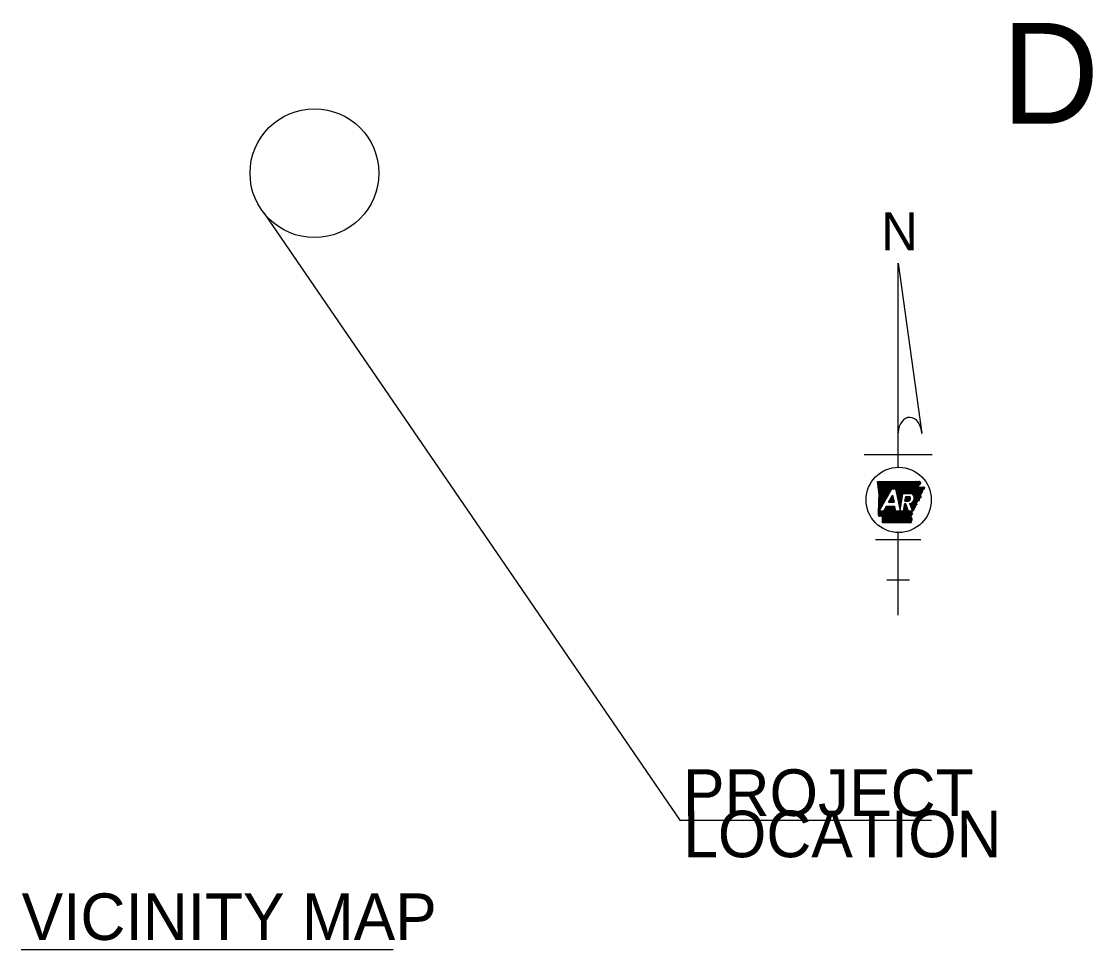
# Model space of a CAD drawing. Extents: x 171 to 3403, y 68 to 2102.
# Drawn here: x 430 to 1255, y 1234 to 1952 of the extents above; entities that cross this region are included whole.
import ezdxf

# ---------------------------------------------------------------- set-up
doc = ezdxf.new("R2010")
doc.units = 0
for name, color, linetype in [('1', 7, 'Continuous'), ('2', 7, 'Continuous'), ('R_Draft', 7, 'Continuous')]:
    doc.layers.add(name, color=color, linetype=linetype)

msp = doc.modelspace()

# ---------------------------------------------------------------- linework, layer by layer
at = {"layer": '1'}
for p, q in [((617.82, 1803.59), (939.58, 1334.32)), ((939.58, 1334.32), (1134.19, 1334.32)), ((430.38, 1234.3), (717.82, 1234.3))]:
    msp.add_line(p, q, dxfattribs=at)
msp.add_circle((656.98, 1834.34), 49.79, dxfattribs=at)
at = {"layer": 'R_Draft'}
for p, q in [((1108.29, 1764.75), (1126.48, 1633.28)), ((1108.29, 1607.09), (1108.29, 1764.75)), ((1081.96, 1616.84), (1134.61, 1616.84)), ((1092.32, 1595.8), (1092.53, 1596.02)), ((1092.39, 1595.18), (1093.23, 1596.02)), ((1092.47, 1594.56), (1093.93, 1596.02)), ((1092.55, 1593.94), (1094.62, 1596.02)), ((1092.63, 1593.32), (1095.32, 1596.01)), ((1092.7, 1592.7), (1096.02, 1596.01)), ((1092.78, 1592.08), (1096.71, 1596.01)), ((1092.86, 1591.46), (1097.41, 1596.01)), ((1092.93, 1590.84), (1098.11, 1596.01)), ((1093.01, 1590.22), (1098.8, 1596.01)), ((1093.09, 1589.6), (1099.5, 1596.01)), ((1093.17, 1588.98), (1100.2, 1596.01)), ((1093.24, 1588.36), (1100.89, 1596.01)), ((1093.32, 1587.74), (1101.59, 1596.01)), ((1093.34, 1580.8), (1108.57, 1596.02)), ((1093.37, 1581.52), (1107.87, 1596.02)), ((1093.39, 1582.24), (1107.17, 1596.02)), ((1093.4, 1587.12), (1102.29, 1596.01)), ((1093.42, 1582.96), (1106.48, 1596.02)), ((1093.44, 1583.68), (1105.78, 1596.02)), ((1093.46, 1584.4), (1105.08, 1596.02)), ((1093.47, 1586.5), (1102.98, 1596.01)), ((1093.49, 1585.12), (1104.38, 1596.02)), ((1093.51, 1585.84), (1103.68, 1596.01)), ((1103.69, 1590.45), (1109.27, 1596.03)), ((1104.39, 1590.45), (1109.97, 1596.03)), ((1105.09, 1590.45), (1110.67, 1596.03)), ((1105.78, 1590.45), (1111.38, 1596.04)), ((1106.22, 1590.19), (1112.09, 1596.06)), ((1106.34, 1589.61), (1112.79, 1596.07)), ((1106.46, 1589.04), (1113.5, 1596.08)), ((1106.59, 1588.46), (1114.21, 1596.09)), ((1106.71, 1587.89), (1114.92, 1596.1)), ((1106.83, 1587.32), (1115.63, 1596.11)), ((1106.95, 1586.74), (1116.33, 1596.12)), ((1107.08, 1586.17), (1117.04, 1596.13)), ((1107.2, 1585.59), (1117.75, 1596.14)), ((1107.32, 1585.02), (1118.46, 1596.15)), ((1107.45, 1584.45), (1119.16, 1596.17)), ((1107.57, 1583.87), (1119.87, 1596.18)), ((1107.69, 1583.3), (1120.58, 1596.19)), ((1107.81, 1582.72), (1121.3, 1596.21)), ((1112.66, 1586.87), (1122.01, 1596.22)), ((1113.35, 1586.87), (1122.72, 1596.24)), ((1114.05, 1586.87), (1123.44, 1596.26)), ((1114.75, 1586.87), (1124.15, 1596.27)), ((1115.44, 1586.87), (1124.86, 1596.29)), ((1116.14, 1586.87), (1125.02, 1595.75)), ((1116.84, 1586.87), (1125.36, 1595.39)), ((1117.53, 1586.87), (1125.45, 1594.78)), ((1118.23, 1586.87), (1123.85, 1592.49)), ((1118.86, 1586.8), (1123.72, 1591.66)), ((1119.24, 1586.49), (1124.45, 1591.7)), ((1119.58, 1586.13), (1125.19, 1591.73)), ((1119.88, 1585.74), (1125.92, 1591.77)), ((1120.14, 1585.3), (1126.66, 1591.81)), ((1120.36, 1584.81), (1127.39, 1591.85)), ((1120.52, 1584.28), (1128.05, 1591.81)), ((1120.61, 1583.67), (1128.38, 1591.44)), ((1093.22, 1577.19), (1099.08, 1583.05)), ((1093.25, 1577.91), (1099.99, 1584.66)), ((1093.27, 1578.64), (1100.9, 1586.27)), ((1093.3, 1579.36), (1101.81, 1587.87)), ((1093.32, 1580.08), (1102.72, 1589.48)), ((1093.55, 1573.28), (1103.27, 1590.45)), ((1100.7, 1580.02), (1103.88, 1585.64)), ((1100.74, 1580.02), (1104.32, 1583.6)), ((1101.43, 1580.02), (1104.44, 1583.03)), ((1101.57, 1581.55), (1104.19, 1584.18)), ((1102.48, 1583.16), (1104.07, 1584.75)), ((1103.27, 1590.45), (1106.16, 1590.45)), ((1103.39, 1584.76), (1103.95, 1585.32)), ((1107.94, 1582.15), (1111.89, 1586.1)), ((1108.06, 1581.58), (1111.74, 1585.26)), ((1108.18, 1581), (1111.6, 1584.42)), ((1108.31, 1580.43), (1111.45, 1583.57)), ((1112.02, 1586.87), (1118.78, 1586.87)), ((1113.49, 1580.78), (1117.16, 1584.45)), ((1113.64, 1581.62), (1116.46, 1584.45)), ((1113.78, 1582.46), (1115.77, 1584.45)), ((1113.93, 1583.31), (1115.07, 1584.45)), ((1114.08, 1584.15), (1114.37, 1584.45)), ((1114.13, 1584.45), (1117.3, 1584.45)), ((1114.19, 1580.78), (1117.55, 1584.14)), ((1114.89, 1580.78), (1117.78, 1583.67)), ((1115.58, 1580.78), (1117.91, 1583.11)), ((1117.59, 1577.87), (1125.32, 1585.59)), ((1117.78, 1577.36), (1125.45, 1585.03)), ((1117.97, 1576.85), (1125.58, 1584.46)), ((1118.16, 1576.34), (1125.71, 1583.89)), ((1119.86, 1580.84), (1125.19, 1586.16)), ((1120.47, 1582.14), (1126.79, 1588.46)), ((1120.62, 1582.98), (1126.71, 1589.08)), ((1126.01, 1586.99), (1126.87, 1587.85)), ((1128.07, 1590.44), (1128.7, 1591.07)), ((1093.1, 1573.59), (1094.54, 1575.02)), ((1093.13, 1574.31), (1095.45, 1576.63)), ((1093.15, 1575.03), (1096.36, 1578.23)), ((1093.18, 1575.75), (1097.26, 1579.84)), ((1093.2, 1576.47), (1098.17, 1581.45)), ((1093.26, 1569.56), (1100.58, 1576.88)), ((1093.67, 1569.28), (1101.28, 1576.88)), ((1094.17, 1569.08), (1101.97, 1576.88)), ((1095, 1569.21), (1102.67, 1576.88)), ((1095.71, 1569.22), (1103.37, 1576.88)), ((1096.25, 1569.07), (1104.06, 1576.88)), ((1096.28, 1567.7), (1105.46, 1576.88)), ((1096.28, 1568.4), (1104.76, 1576.88)), ((1096.28, 1567.01), (1105.83, 1576.55)), ((1096.28, 1566.31), (1105.95, 1575.98)), ((1096.28, 1565.62), (1106.07, 1575.41)), ((1096.28, 1564.92), (1106.19, 1574.83)), ((1098.93, 1576.88), (1096.89, 1573.28)), ((1097.68, 1574.68), (1099.88, 1576.88)), ((1098.59, 1576.28), (1099.19, 1576.88)), ((1105.75, 1576.88), (1098.93, 1576.88)), ((1100.7, 1580.02), (1105.08, 1580.02)), ((1102.13, 1580.02), (1104.56, 1582.45)), ((1102.83, 1580.02), (1104.69, 1581.88)), ((1103.25, 1564.23), (1115.24, 1576.21)), ((1103.52, 1580.02), (1104.81, 1581.31)), ((1103.95, 1564.22), (1115.43, 1575.7)), ((1104.22, 1580.02), (1104.93, 1580.73)), ((1104.64, 1564.22), (1115.62, 1575.19)), ((1104.92, 1580.02), (1105.05, 1580.16)), ((1105.34, 1564.22), (1115.8, 1574.69)), ((1108.43, 1579.85), (1111.3, 1582.73)), ((1108.55, 1579.28), (1111.16, 1581.88)), ((1108.67, 1578.71), (1111.01, 1581.04)), ((1108.8, 1578.13), (1110.86, 1580.2)), ((1108.92, 1577.56), (1110.71, 1579.35)), ((1109.04, 1576.98), (1110.57, 1578.51)), ((1109.17, 1576.41), (1110.42, 1577.67)), ((1109.29, 1575.84), (1110.27, 1576.82)), ((1109.41, 1575.26), (1110.13, 1575.98)), ((1109.53, 1574.69), (1109.98, 1575.13)), ((1112.3, 1573.97), (1115.05, 1576.72)), ((1112.45, 1574.82), (1114.86, 1577.23)), ((1112.6, 1575.66), (1114.68, 1577.74)), ((1112.74, 1576.51), (1114.49, 1578.25)), ((1112.89, 1577.35), (1114.28, 1578.74)), ((1113.04, 1578.19), (1113.59, 1578.74)), ((1114.3, 1578.74), (1113.13, 1578.74)), ((1113.49, 1580.78), (1116.39, 1580.78)), ((1116.32, 1573.28), (1114.3, 1578.74)), ((1116.28, 1580.78), (1117.85, 1582.35)), ((1117.16, 1579.03), (1119.29, 1573.28)), ((1117.22, 1578.89), (1117.43, 1579.1)), ((1117.4, 1578.38), (1118.73, 1579.7)), ((1118.34, 1575.83), (1122.53, 1580.01)), ((1118.53, 1575.32), (1122.45, 1579.24)), ((1118.72, 1574.82), (1122.37, 1578.46)), ((1118.91, 1574.31), (1121.05, 1576.44)), ((1119.1, 1573.8), (1120.75, 1575.45)), ((1123.33, 1580.82), (1124.3, 1581.79)), ((1093, 1570), (1096.28, 1573.28)), ((1093.01, 1570.71), (1095.58, 1573.28)), ((1093.03, 1571.43), (1094.89, 1573.28)), ((1093.06, 1572.15), (1094.19, 1573.28)), ((1093.08, 1572.87), (1093.63, 1573.41)), ((1096.89, 1573.28), (1093.55, 1573.28)), ((1096.3, 1564.24), (1106.32, 1574.26)), ((1096.99, 1564.24), (1106.44, 1573.68)), ((1097.69, 1564.24), (1106.73, 1573.28)), ((1098.38, 1564.23), (1107.43, 1573.28)), ((1099.08, 1564.23), (1108.13, 1573.28)), ((1099.77, 1564.23), (1108.82, 1573.28)), ((1100.47, 1564.23), (1109.52, 1573.28)), ((1101.17, 1564.23), (1110.22, 1573.28)), ((1101.86, 1564.23), (1110.92, 1573.28)), ((1102.56, 1564.23), (1111.61, 1573.28)), ((1106.04, 1564.22), (1115.99, 1574.18)), ((1112.18, 1573.28), (1106.53, 1573.28)), ((1106.73, 1564.22), (1116.18, 1573.67)), ((1107.43, 1564.22), (1116.49, 1573.28)), ((1108.12, 1564.22), (1117.19, 1573.28)), ((1108.82, 1564.22), (1117.88, 1573.28)), ((1109.51, 1564.22), (1118.58, 1573.28)), ((1109.66, 1574.11), (1109.83, 1574.29)), ((1110.21, 1564.21), (1118.81, 1572.82)), ((1110.91, 1564.21), (1118.85, 1572.15)), ((1111.6, 1564.21), (1118.88, 1571.49)), ((1112.3, 1564.21), (1118.91, 1570.82)), ((1112.99, 1564.21), (1117.76, 1568.98)), ((1113.69, 1564.21), (1117.98, 1568.5)), ((1114.38, 1564.21), (1118.19, 1568.02)), ((1115.08, 1564.21), (1118.41, 1567.53)), ((1115.78, 1564.21), (1118.62, 1567.05)), ((1119.29, 1573.28), (1116.32, 1573.28)), ((1116.47, 1564.2), (1118.8, 1566.54)), ((1117.17, 1564.2), (1118.49, 1565.52)), ((1117.86, 1564.2), (1118.17, 1564.51)), ((1090.74, 1551.22), (1125.84, 1551.22)), ((1108.29, 1492.67), (1108.29, 1556.66)), ((1099.51, 1520.05), (1117.06, 1520.05))]:
    msp.add_line(p, q, dxfattribs=at)
for points in [[(1092.29, 1596.01), (1101.9, 1596.01), (1110.34, 1596.03), (1120.29, 1596.18), (1124.91, 1596.29)], [(1092.29, 1596.02), (1101.9, 1596.01), (1110.34, 1596.03), (1120.29, 1596.18), (1124.91, 1596.29)], [(1092.99, 1570), (1093.52, 1586.14), (1092.29, 1596.02)], [(1093.35, 1581.07), (1093.52, 1586.14), (1092.29, 1596.01)], [(1127.93, 1591.87), (1128.76, 1591), (1126.69, 1589.3), (1126.91, 1587.58), (1125.13, 1586.4), (1125.74, 1583.76), (1124.37, 1582.51), (1124.25, 1581.15), (1122.58, 1580.55), (1122.32, 1577.98), (1121.12, 1576.7), (1120.54, 1574.76), (1118.8, 1573.17), (1118.93, 1570.35), (1117.74, 1569.02), (1118.82, 1566.6), (1118.08, 1564.2)], [(1123.48, 1591.65), (1127.99, 1591.88)], [(1123.48, 1591.65), (1127.99, 1591.88)], [(1103.88, 1585.64), (1105.08, 1580.02)], [(1106.16, 1590.45), (1109.74, 1573.74), (1112.02, 1586.87)], [(1113.49, 1580.78), (1114.13, 1584.45)], [(1092.99, 1570), (1093.35, 1581.07)], [(1106.53, 1573.28), (1105.75, 1576.88)], [(1113.13, 1578.74), (1112.18, 1573.28)], [(1118.08, 1564.2), (1096.29, 1564.24), (1096.27, 1569.05)], [(1118.07, 1564.2), (1096.29, 1564.24), (1096.28, 1569.05)]]:
    msp.add_lwpolyline(points, dxfattribs=at)
for centre, major_axis, ratio, start_param, end_param in [((1117.38, 1632.99), (-0.39, 12.64), 0.719778, 4.712385, 7.768526), ((1115.69, 1582.9), (-2.23, 0), 0.999987, 1.887169, 3.90762), ((1116.27, 1583.3), (-4.36, 0), 0.999987, 1.777838, 4.099264)]:
    msp.add_ellipse(centre, major_axis=major_axis, ratio=ratio, start_param=start_param, end_param=end_param, dxfattribs=at)
msp.add_ellipse((1108.7, 1581.88), major_axis=(25.22, 0), ratio=0.999976, dxfattribs=at)
for points in [[(1124.91, 1596.29), (1124.94, 1596.03), (1125.02, 1595.89), (1125.03, 1595.64), (1125.13, 1595.53), (1125.31, 1595.43), (1125.46, 1595.26), (1125.5, 1595.06), (1125.45, 1594.85), (1125.44, 1594.61), (1125.41, 1594.41), (1125.37, 1594.23), (1125.23, 1594.08), (1125.1, 1593.97), (1124.97, 1593.85), (1124.88, 1593.71), (1124.73, 1593.58), (1124.58, 1593.42), (1124.45, 1593.29), (1124.32, 1593.13), (1124.26, 1592.94), (1124.13, 1592.81), (1124.02, 1592.69), (1123.88, 1592.53), (1123.81, 1592.37), (1123.67, 1592.19), (1123.64, 1592.01), (1123.55, 1591.87), (1123.55, 1591.84)], [(1124.91, 1596.29), (1124.94, 1596.03), (1125.02, 1595.89), (1125.03, 1595.64), (1125.13, 1595.54), (1125.31, 1595.43), (1125.46, 1595.26), (1125.5, 1595.05), (1125.45, 1594.85), (1125.44, 1594.61), (1125.41, 1594.41), (1125.38, 1594.23), (1125.24, 1594.08), (1125.1, 1593.97), (1124.97, 1593.85), (1124.88, 1593.72), (1124.73, 1593.57), (1124.58, 1593.42), (1124.45, 1593.29), (1124.33, 1593.13), (1124.27, 1592.94), (1124.13, 1592.81), (1124.02, 1592.69), (1123.88, 1592.53), (1123.81, 1592.37), (1123.67, 1592.19), (1123.64, 1592.01), (1123.55, 1591.87), (1123.55, 1591.84)], [(1127.93, 1591.87), (1127.99, 1591.88), (1128.19, 1591.67), (1128.28, 1591.48), (1128.42, 1591.39), (1128.57, 1591.33), (1128.68, 1591.2), (1128.75, 1591.05), (1128.71, 1590.91), (1128.55, 1590.9), (1128.36, 1590.87), (1128.18, 1590.88), (1128.04, 1590.76), (1128.17, 1590.6), (1128.34, 1590.45), (1128.39, 1590.29), (1128.3, 1590.14), (1128.11, 1590.05), (1127.92, 1589.98), (1127.76, 1589.84), (1127.68, 1589.7), (1127.49, 1589.64), (1127.3, 1589.59), (1127.14, 1589.57), (1126.95, 1589.53), (1126.76, 1589.44), (1126.69, 1589.29), (1126.71, 1589.07), (1126.7, 1588.84), (1126.9, 1588.76), (1127.07, 1588.76), (1127.24, 1588.67), (1127.22, 1588.54), (1127.1, 1588.37), (1126.95, 1588.24), (1126.8, 1588.18), (1126.66, 1588.05), (1126.71, 1587.92), (1126.83, 1587.84), (1126.92, 1587.71), (1126.91, 1587.58), (1126.77, 1587.49), (1126.61, 1587.53), (1126.5, 1587.68), (1126.37, 1587.72), (1126.26, 1587.78), (1126.13, 1587.7), (1126.13, 1587.53), (1126.08, 1587.34), (1126.12, 1587.21), (1126.17, 1587.02), (1126.17, 1586.87), (1126.12, 1586.67), (1126.02, 1586.46), (1125.9, 1586.4), (1125.85, 1586.62), (1125.83, 1586.81), (1125.76, 1586.92), (1125.66, 1586.92), (1125.54, 1586.83), (1125.4, 1586.69), (1125.23, 1586.54), (1125.13, 1586.4), (1125.18, 1586.21), (1125.31, 1586.17), (1125.41, 1586.2), (1125.47, 1586.32), (1125.56, 1586.34), (1125.66, 1586.15)], [(1125.66, 1586.15), (1125.69, 1585.98), (1125.59, 1585.8), (1125.55, 1585.61), (1125.56, 1585.43), (1125.37, 1585.33), (1125.21, 1585.21), (1125.31, 1585.06), (1125.49, 1584.93), (1125.66, 1584.84), (1125.77, 1584.73), (1125.8, 1584.49), (1125.83, 1584.33), (1125.9, 1584.12), (1125.92, 1583.97), (1125.81, 1583.79), (1125.69, 1583.76), (1125.55, 1583.8), (1125.4, 1583.81), (1125.28, 1583.7), (1125.19, 1583.52), (1125.1, 1583.36), (1125.03, 1583.22), (1124.96, 1583.06), (1124.84, 1582.88), (1124.68, 1582.85), (1124.49, 1582.8), (1124.37, 1582.68), (1124.39, 1582.45), (1124.5, 1582.31), (1124.58, 1582.12), (1124.64, 1581.96), (1124.61, 1581.76), (1124.53, 1581.61), (1124.42, 1581.52), (1124.37, 1581.33), (1124.29, 1581.19), (1124.22, 1581.14), (1124.08, 1581.15), (1123.93, 1581.18), (1123.8, 1581.17), (1123.67, 1581.11), (1123.55, 1581.15), (1123.42, 1581.29), (1123.31, 1581.4), (1123.19, 1581.44), (1123.06, 1581.37), (1123.04, 1581.17), (1123.1, 1580.97), (1123.15, 1580.7), (1123.1, 1580.54), (1123.08, 1580.26)], [(1123.08, 1580.26), (1122.88, 1580.1), (1122.78, 1579.94), (1122.25, 1579.99), (1122.27, 1579.8), (1122.08, 1579.7), (1121.91, 1579.58), (1122.01, 1579.44), (1122.19, 1579.31), (1122.36, 1579.21), (1122.48, 1579.11), (1122.5, 1578.86), (1122.54, 1578.71), (1122.6, 1578.49), (1122.62, 1578.34), (1122.51, 1578.17), (1122.39, 1578.13), (1122.26, 1578.17), (1122.1, 1578.18), (1121.98, 1578.07), (1121.89, 1577.9), (1121.8, 1577.73), (1121.73, 1577.59), (1121.66, 1577.43), (1121.54, 1577.25), (1121.38, 1577.23), (1121.19, 1577.18), (1121.07, 1577.05), (1121.09, 1576.83), (1121.2, 1576.68), (1121.28, 1576.49), (1121.34, 1576.34), (1121.32, 1576.13), (1121.23, 1575.98), (1121.12, 1575.89), (1121.07, 1575.7), (1121, 1575.56), (1120.93, 1575.51), (1120.78, 1575.53), (1120.63, 1575.56), (1120.5, 1575.54), (1120.38, 1575.48), (1120.25, 1575.52), (1120.12, 1575.66), (1120.01, 1575.77), (1119.89, 1575.81), (1119.76, 1575.75), (1119.74, 1575.55), (1119.8, 1575.35), (1119.86, 1575.07), (1119.8, 1574.91), (1119.79, 1574.63)], [(1096.28, 1569.05), (1096.3, 1569.04), (1096.19, 1569.11), (1096.03, 1569.19), (1095.86, 1569.2), (1095.64, 1569.23), (1095.45, 1569.25), (1095.26, 1569.37), (1095.06, 1569.25), (1094.84, 1569.15), (1094.7, 1569.26), (1094.53, 1569.18), (1094.41, 1569.22), (1094.21, 1569.08), (1094.01, 1569.13), (1093.87, 1569.09), (1093.69, 1569.09), (1093.65, 1569.3), (1093.48, 1569.33), (1093.33, 1569.41), (1093.23, 1569.62), (1093.16, 1569.78), (1092.99, 1570)], [(1096.27, 1569.05), (1096.3, 1569.04), (1096.18, 1569.11), (1096.03, 1569.19), (1095.86, 1569.2), (1095.64, 1569.23), (1095.45, 1569.25), (1095.26, 1569.37), (1095.06, 1569.24), (1094.83, 1569.15), (1094.7, 1569.26), (1094.53, 1569.18), (1094.41, 1569.22), (1094.2, 1569.08), (1094.01, 1569.13), (1093.87, 1569.09), (1093.69, 1569.09), (1093.65, 1569.3), (1093.48, 1569.33), (1093.33, 1569.41), (1093.23, 1569.62), (1093.16, 1569.78), (1092.99, 1570)], [(1118.98, 1572.4), (1118.93, 1572.26), (1118.86, 1572.02), (1118.88, 1571.82), (1118.97, 1571.65), (1119.11, 1571.55), (1119.27, 1571.42), (1119.25, 1571.21), (1119.16, 1571.13), (1118.95, 1571.18), (1118.79, 1571.26), (1118.66, 1571.21), (1118.48, 1571.12), (1118.34, 1571.1), (1118.34, 1570.82), (1118.53, 1570.62), (1118.69, 1570.62), (1118.87, 1570.59), (1118.94, 1570.38), (1118.83, 1570.2), (1118.65, 1570.11), (1118.43, 1570.22), (1118.27, 1570.33), (1118.11, 1570.44), (1117.91, 1570.49), (1117.79, 1570.47), (1117.74, 1570.22), (1117.83, 1569.99), (1117.99, 1569.84), (1118.13, 1569.64), (1118.11, 1569.48), (1118, 1569.45), (1117.81, 1569.4), (1117.7, 1569.35), (1117.67, 1569.3), (1117.73, 1569.09), (1117.78, 1568.88), (1117.78, 1568.71), (1117.71, 1568.56), (1117.61, 1568.32), (1117.62, 1568.17), (1117.7, 1568.09), (1117.78, 1568.11), (1117.91, 1568.2), (1117.98, 1568.29), (1118.05, 1568.41), (1118.17, 1568.51), (1118.32, 1568.42), (1118.36, 1568.24), (1118.27, 1568.08), (1118.15, 1568), (1117.99, 1567.95), (1117.88, 1567.82), (1117.91, 1567.66), (1118, 1567.58), (1118.22, 1567.62), (1118.37, 1567.69), (1118.45, 1567.77), (1118.55, 1567.87), (1118.6, 1567.97), (1118.68, 1568.08), (1118.82, 1568.11), (1118.89, 1568.02), (1118.86, 1567.82), (1118.78, 1567.62), (1118.66, 1567.47), (1118.54, 1567.36), (1118.38, 1567.11), (1118.42, 1566.89), (1118.48, 1566.7), (1118.55, 1566.56), (1118.7, 1566.58), (1118.86, 1566.6), (1118.95, 1566.53), (1118.94, 1566.36), (1118.83, 1566.2), (1118.71, 1566.04), (1118.65, 1565.83), (1118.68, 1565.68), (1118.68, 1565.55), (1118.63, 1565.39), (1118.55, 1565.31), (1118.32, 1565.32), (1118.09, 1565.34), (1117.97, 1565.27), (1117.99, 1565.07), (1118.13, 1564.92), (1118.22, 1564.84), (1118.36, 1564.68), (1118.42, 1564.54), (1118.4, 1564.42), (1118.32, 1564.32), (1118.07, 1564.2)], [(1118.98, 1572.4), (1118.93, 1572.26), (1118.86, 1572.02), (1118.88, 1571.82), (1118.97, 1571.65), (1119.11, 1571.55), (1119.27, 1571.42), (1119.25, 1571.21), (1119.16, 1571.13), (1118.95, 1571.18), (1118.79, 1571.26), (1118.66, 1571.21), (1118.48, 1571.12), (1118.34, 1571.1), (1118.34, 1570.82), (1118.53, 1570.62), (1118.69, 1570.62), (1118.87, 1570.59), (1118.94, 1570.38), (1118.83, 1570.2), (1118.65, 1570.11), (1118.43, 1570.22), (1118.27, 1570.33), (1118.11, 1570.44), (1117.91, 1570.49), (1117.79, 1570.47), (1117.74, 1570.22), (1117.83, 1569.99), (1117.99, 1569.84), (1118.13, 1569.64), (1118.11, 1569.48), (1118, 1569.45), (1117.81, 1569.4), (1117.7, 1569.35), (1117.67, 1569.3), (1117.73, 1569.09), (1117.78, 1568.88), (1117.78, 1568.71), (1117.71, 1568.56), (1117.61, 1568.32), (1117.62, 1568.17), (1117.7, 1568.09), (1117.78, 1568.11), (1117.91, 1568.2), (1117.98, 1568.29), (1118.05, 1568.41), (1118.17, 1568.51), (1118.32, 1568.42), (1118.36, 1568.24), (1118.27, 1568.08), (1118.15, 1568), (1117.99, 1567.95), (1117.88, 1567.82), (1117.91, 1567.66), (1118, 1567.58), (1118.22, 1567.62), (1118.37, 1567.69), (1118.45, 1567.77), (1118.55, 1567.87), (1118.6, 1567.97), (1118.68, 1568.08), (1118.82, 1568.11), (1118.89, 1568.02), (1118.86, 1567.82), (1118.78, 1567.62), (1118.66, 1567.47), (1118.54, 1567.36), (1118.38, 1567.11), (1118.42, 1566.89), (1118.48, 1566.7), (1118.55, 1566.56), (1118.7, 1566.58), (1118.86, 1566.6), (1118.95, 1566.53), (1118.94, 1566.36), (1118.83, 1566.2), (1118.71, 1566.04), (1118.65, 1565.83), (1118.68, 1565.68), (1118.68, 1565.55), (1118.63, 1565.39), (1118.55, 1565.31), (1118.32, 1565.32), (1118.09, 1565.34), (1117.97, 1565.27), (1117.99, 1565.07), (1118.13, 1564.92), (1118.22, 1564.84), (1118.36, 1564.68), (1118.42, 1564.54), (1118.4, 1564.42), (1118.32, 1564.32), (1118.07, 1564.2)], [(1119.79, 1574.63), (1119.77, 1574.62), (1119.66, 1574.49), (1119.72, 1574.28), (1119.96, 1574.2), (1120.06, 1574), (1120.07, 1573.82), (1119.99, 1573.57), (1119.88, 1573.46), (1119.68, 1573.41), (1119.52, 1573.38), (1119.49, 1573.11), (1119.42, 1572.97), (1119.3, 1572.93), (1119.12, 1573.02), (1119.01, 1573.06), (1118.88, 1573.12), (1118.71, 1573.22), (1118.59, 1573.2), (1118.62, 1572.94), (1118.63, 1572.93), (1118.78, 1572.73), (1118.92, 1572.58), (1118.98, 1572.4)], [(1119.79, 1574.63), (1119.77, 1574.62), (1119.66, 1574.49), (1119.72, 1574.28), (1119.96, 1574.2), (1120.06, 1574), (1120.07, 1573.82), (1119.99, 1573.57), (1119.88, 1573.46), (1119.68, 1573.41), (1119.52, 1573.38), (1119.49, 1573.11), (1119.42, 1572.97), (1119.3, 1572.93), (1119.12, 1573.02), (1119.01, 1573.06), (1118.88, 1573.12), (1118.71, 1573.22), (1118.59, 1573.2), (1118.62, 1572.94), (1118.63, 1572.93), (1118.78, 1572.73), (1118.92, 1572.58), (1118.98, 1572.4)]]:
    msp.add_spline(points, degree=3, dxfattribs=at)

# ---------------------------------------------------------------- texts
at = {"layer": '2'}
for s, height, p in [('DITCH NO.  30 STR.  & APPRS.', 78, (1188.38, 1872.54)), ('PROJECT', 36, (941.98, 1337.66)), ('LOCATION', 36, (942.15, 1305.69)), ('VICINITY MAP', 36, (430.61, 1241.77))]:
    msp.add_text(s, height=height, dxfattribs=at).set_placement(p)
at = {"layer": 'R_Draft'}
for s, height, p in [('N', 29.34, (1095.21, 1774.67)), ('STS 10-03-17', 0.7292, (1106.29, 1556.86))]:
    msp.add_text(s, height=height, dxfattribs=at).set_placement(p)

doc.saveas('drawing.dxf')
